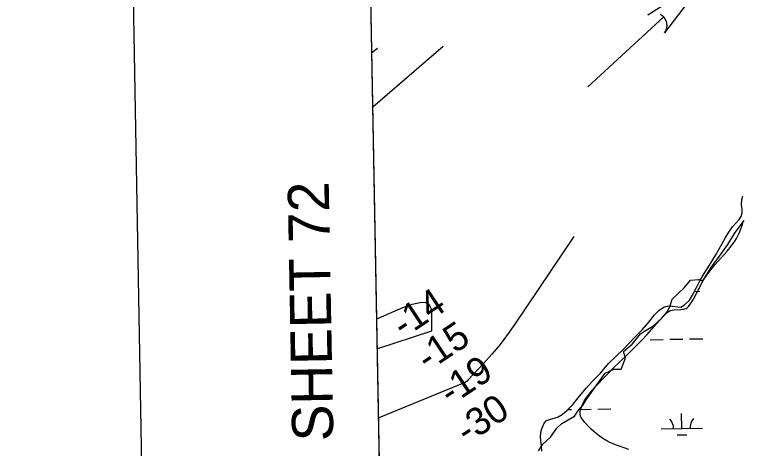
# Model space of a CAD drawing. Extents: x 3957609 to 3995875, y 234277 to 260273.
# Drawn here: x 3960953 to 3962722, y 241513 to 242568 of the extents above; entities that cross this region are included whole.
import ezdxf

# ---------------------------------------------------------------- set-up
doc = ezdxf.new("R2010")
doc.units = 0
for name, color, linetype in [('V-ANNO-SYMB', 7, 'Continuous'), ('V-ANNO-TEXT', 7, 'Continuous'), ('V-GRID-FRAM', 7, 'Continuous'), ('V-RIVR-EDGE', 7, 'Continuous'), ('V-RIVR-RANG', 7, 'Continuous'), ('V-SITE-VEGE', 7, 'Continuous'), ('V-STRM-FLOW', 7, 'Continuous'), ('V-TOPO-MINR', 7, 'Continuous'), ('V-WETL-SWMP', 7, 'Continuous')]:
    doc.layers.add(name, color=color, linetype=linetype)

msp = doc.modelspace()

# ---------------------------------------------------------------- linework, layer by layer
at = {"layer": 'V-ANNO-SYMB'}
msp.add_lwpolyline([(3961369.919, 235535.518), (3994447.652, 236136.973), (3994031.027, 259049.761), (3960953.294, 258448.306), (3961369.919, 235535.518)], dxfattribs=at)
at = {"layer": 'V-GRID-FRAM'}
for points in [[(3961534.646, 257877.621), (3993438.57, 258485.581), (3993792.928, 240306.336), (3961873.139, 239698.074), (3961534.646, 257877.621)], [(3961873.139, 239698.074), (3961534.646, 257877.621)]]:
    msp.add_lwpolyline(points, dxfattribs=at)
at = {"layer": 'V-RIVR-EDGE'}
msp.add_lwpolyline([(3962226.19, 241507.633), (3962236.605, 241523.729), (3962255.542, 241540.773), (3962270.692, 241562.551), (3962283.001, 241573.913), (3962313.301, 241591.904), (3962321.823, 241604.213), (3962335.079, 241619.363), (3962341.707, 241631.672), (3962388.103, 241696.059), (3962408.934, 241706.474), (3962426.925, 241706.474), (3962437.34, 241732.986), (3962432.606, 241749.083), (3962453.437, 241767.074), (3962474.268, 241791.692), (3962483.737, 241798.32), (3962503.621, 241810.629), (3962525.399, 241829.567), (3962539.602, 241846.61), (3962546.23, 241859.866), (3962550.964, 241875.963), (3962580.317, 241903.422), (3962595.467, 241922.359), (3962615.351, 241924.253), (3962625.767, 241920.466), (3962647.544, 241955.5), (3962665.535, 241981.065), (3962686.366, 242009.471), (3962702.463, 242035.983), (3962726.134, 242067.23)], dxfattribs=at)
at = {"layer": 'V-SITE-VEGE'}
for points in [[(3962370.457, 241546.306), (3962365.755, 241550.134), (3962360.42, 241554.803), (3962354.325, 241560.542), (3962351.063, 241563.79), (3962339.031, 241576.443), (3962336.374, 241579.496), (3962333.173, 241583.59), (3962331.574, 241585.941), (3962330.003, 241588.638), (3962328.594, 241591.733), (3962328.037, 241593.386), (3962327.605, 241595.151), (3962327.343, 241597.039), (3962327.308, 241599.055), (3962327.697, 241603.05), (3962328.469, 241607.095), (3962329.184, 241609.815), (3962330.368, 241613.462), (3962332.323, 241618.355), (3962335.252, 241624.364), (3962337.29, 241628.026), (3962339.823, 241632.197), (3962342.953, 241636.936), (3962346.782, 241642.294), (3962351.411, 241648.313), (3962356.916, 241655.01), (3962363.31, 241662.366), (3962372.462, 241672.424), (3962381.658, 241682.144), (3962396.02, 241696.72), (3962406.987, 241707.494), (3962441.037, 241740.27), (3962452.064, 241751.063), (3962464.569, 241763.665), (3962476.91, 241776.622), (3962489.063, 241789.816), (3962513.176, 241816.444), (3962529.403, 241834.009), (3962538.827, 241843.856), (3962541.009, 241845.742), (3962543.435, 241847.231), (3962545.174, 241848.03), (3962547.628, 241848.878), (3962551.097, 241849.683), (3962555.998, 241850.315), (3962571.931, 241851.096), (3962576.914, 241851.669), (3962579.445, 241852.171), (3962582.02, 241852.898), (3962584.594, 241853.94), (3962587.117, 241855.403), (3962588.317, 241856.316), (3962589.477, 241857.385), (3962590.58, 241858.628), (3962594.699, 241864.092), (3962598.52, 241869.755), (3962600.929, 241873.624), (3962603.995, 241878.877), (3962607.88, 241886.012), (3962619.345, 241908.548), (3962623.178, 241915.808), (3962627.799, 241923.906), (3962630.41, 241928.115), (3962633.334, 241932.494), (3962639.003, 241940.26), (3962644.998, 241947.849), (3962649.135, 241952.832), (3962654.793, 241959.408), (3962678.001, 241985.486), (3962684.493, 241993.055), (3962691.655, 242001.874), (3962695.327, 242006.672), (3962699.106, 242011.88), (3962702.952, 242017.547), (3962706.823, 242023.738), (3962710.646, 242030.529), (3962714.341, 242038.011), (3962717.077, 242044.572), (3962719.406, 242051.259), (3962720.776, 242055.773), (3962722.429, 242061.851)], [(3962445.723, 241510.536), (3962433.968, 241514.489), (3962420.619, 241519.324), (3962413.551, 241522.085), (3962406.066, 241525.191), (3962399.828, 241528.018), (3962393.823, 241531.045), (3962389.932, 241533.185), (3962384.867, 241536.193), (3962378.295, 241540.51), (3962374.615, 241543.142), (3962370.457, 241546.306)]]:
    msp.add_lwpolyline(points, dxfattribs=at)
at = {"layer": 'V-STRM-FLOW'}
msp.add_line((3962346.251, 242392.61), (3962530.315, 242562.375), dxfattribs=at)
msp.add_lwpolyline([(3962492.975, 242568.297), (3962492.524, 242568.04), (3962492.107, 242567.792), (3962491.807, 242567.608), (3962491.599, 242567.478), (3962634.402, 242658.376), (3962532.278, 242523.373), (3962533.983, 242525.893), (3962535.381, 242528.476), (3962535.872, 242529.553), (3962536.273, 242530.515), (3962536.71, 242531.703), (3962537.088, 242532.862), (3962537.376, 242533.879), (3962537.713, 242535.284), (3962538.001, 242536.811), (3962538.128, 242537.671), (3962538.255, 242538.782), (3962538.362, 242540.255), (3962538.394, 242541.402), (3962538.38, 242542.635), (3962538.344, 242543.45), (3962538.281, 242544.341), (3962538.166, 242545.425), (3962538.027, 242546.422), (3962537.854, 242547.41), (3962537.69, 242548.213), (3962537.407, 242549.401), (3962537.089, 242550.527), (3962536.804, 242551.419), (3962536.434, 242552.456), (3962536.083, 242553.345), (3962535.75, 242554.124), (3962535.473, 242554.719), (3962535.029, 242555.622), (3962534.544, 242556.532), (3962534.055, 242557.379), (3962533.529, 242558.224), (3962533.018, 242558.99), (3962532.434, 242559.809), (3962531.934, 242560.467), (3962531.188, 242561.386), (3962530.315, 242562.375), (3962530.027, 242562.684), (3962529.597, 242563.127), (3962529.075, 242563.643), (3962528.559, 242564.131), (3962528.045, 242564.591), (3962527.536, 242565.031), (3962526.921, 242565.535), (3962526.486, 242565.876), (3962525.837, 242566.362), (3962525.218, 242566.798), (3962524.785, 242567.093), (3962523.651, 242567.811), (3962523.03, 242568.177), (3962522.598, 242568.417)], dxfattribs=at)
at = {"layer": 'V-TOPO-MINR'}
for points in [[(3961835.051, 242485.777), (3961821.437, 242474.87)], [(3961994.802, 242490.319), (3961823.891, 242343.074)], [(3962312.267, 242028.666), (3962168.78, 241815.344), (3962151.092, 241790.354), (3962132.644, 241765.967), (3962113.056, 241742.487), (3962092.709, 241719.61), (3962054.797, 241678.978), (3962052.725, 241677.029), (3962050.514, 241675.28), (3962048.095, 241673.833), (3962045.537, 241672.586), (3961837.956, 241587.68)], [(3961833.471, 241828.528), (3961896.986, 241856.028), (3961907.983, 241860.303), (3961919.146, 241864.009), (3961930.557, 241866.862), (3961942.133, 241869.147), (3961951.265, 241867.945), (3961958.573, 241864.575), (3961963.142, 241857.951), (3961965.888, 241849.159), (3961966.611, 241800.306), (3961966.539, 241799.801), (3961966.38, 241799.34), (3961965.714, 241798.603), (3961963.759, 241797.654), (3961834.835, 241755.299)]]:
    msp.add_lwpolyline(points, dxfattribs=at)
at = {"layer": 'V-WETL-SWMP'}
for p, q in [((3962719.906, 242118.618), (3962722.332, 242126.735)), ((3962719.499, 242105.059), (3962719.906, 242118.618)), ((3962720.724, 242094.817), (3962719.499, 242105.059)), ((3962718.524, 242077.444), (3962721.276, 242086.39)), ((3962721.276, 242086.39), (3962720.724, 242094.817)), ((3962704.422, 242059.993), (3962713.449, 242069.971)), ((3962713.449, 242069.971), (3962718.524, 242077.444)), ((3962690.49, 242041.715), (3962697.366, 242052.011)), ((3962697.366, 242052.011), (3962704.422, 242059.993)), ((3962680.675, 242025.945), (3962690.49, 242041.715)), ((3962671.524, 242009.684), (3962680.675, 242025.945)), ((3962657.144, 241984.295), (3962671.524, 242009.684)), ((3962641.772, 241958.734), (3962657.144, 241984.295)), ((3962628.682, 241938.313), (3962641.772, 241958.734)), ((3962618.052, 241920.719), (3962628.682, 241938.313)), ((3962610.389, 241904.467), (3962618.052, 241920.719)), ((3962600.097, 241885.884), (3962610.389, 241904.467)), ((3962605.261, 241895.209), (3962618.349, 241895.447)), ((3962593.067, 241873.934), (3962600.097, 241885.884)), ((3962518.176, 241848.973), (3962531.839, 241857.825)), ((3962531.839, 241857.825), (3962543.73, 241859.722)), ((3962543.73, 241859.722), (3962571.856, 241856.436)), ((3962571.856, 241856.436), (3962580.911, 241862.116)), ((3962580.911, 241862.116), (3962593.067, 241873.934)), ((3962507.668, 241837.992), (3962518.176, 241848.973)), ((3962494.394, 241820.381), (3962507.668, 241837.992)), ((3962477.656, 241801.424), (3962494.394, 241820.381)), ((3962460.58, 241783.622), (3962477.656, 241801.424)), ((3962432.012, 241753.676), (3962460.58, 241783.622)), ((3962497.06, 241777.79), (3962529.054, 241778.372)), ((3962545.052, 241778.663), (3962577.046, 241779.245)), ((3962593.044, 241779.535), (3962625.038, 241780.117)), ((3962395.867, 241719.547), (3962432.012, 241753.676)), ((3962376.843, 241696.277), (3962395.867, 241719.547)), ((3962356.641, 241676.305), (3962376.843, 241696.277)), ((3962343.186, 241661.007), (3962356.641, 241676.305)), ((3962318.909, 241632.081), (3962329.566, 241645.542)), ((3962329.566, 241645.542), (3962343.186, 241661.007)), ((3962310.22, 241621.113), (3962318.909, 241632.081)), ((3962295.934, 241606.305), (3962310.22, 241621.113)), ((3962370.2, 241608.955), (3962402.195, 241609.537)), ((3962274.052, 241590.455), (3962283.442, 241595.477)), ((3962283.442, 241595.477), (3962295.934, 241606.305)), ((3962297.21, 241607.628), (3962306.211, 241607.791)), ((3962322.208, 241608.082), (3962354.203, 241608.664)), ((3962574.405, 241561.918), (3962573.75, 241597.912)), ((3962236.193, 241565.407), (3962240.101, 241574.526)), ((3962240.101, 241574.526), (3962245.678, 241581.175)), ((3962245.678, 241581.175), (3962255.077, 241584.874)), ((3962255.077, 241584.874), (3962263.988, 241587.248)), ((3962263.988, 241587.248), (3962274.052, 241590.455)), ((3962231.048, 241543.386), (3962232.945, 241556.624)), ((3962232.945, 241556.624), (3962236.193, 241565.407)), ((3962524.413, 241561.009), (3962624.397, 241562.827)), ((3962231.789, 241531.322), (3962231.048, 241543.386)), ((3962562.687, 241546.271), (3962586.683, 241546.707)), ((3962233.848, 241519.929), (3962231.789, 241531.322)), ((3962234.266, 241506.706), (3962233.848, 241519.929))]:
    msp.add_line(p, q, dxfattribs=at)
for centre, start, end in [((3962519.162, 241561.388), 0.269879, 41.813537), ((3962629.63, 241563.397), 140.269876, 181.813534)]:
    msp.add_arc(centre, 35.246, start, end, dxfattribs=at)

# ---------------------------------------------------------------- texts
at = {"layer": 'V-ANNO-TEXT'}
msp.add_text('JOINS SHEET 72', height=100, rotation=91.041702, dxfattribs=at).set_placement((3961735.838, 241100.638))
at = {"layer": 'V-RIVR-RANG'}
for s, p in [('-14', (3961898.03, 241779.812)), ('-15', (3961957.123, 241699.069)), ('-19', (3962012.67, 241616.022)), ('-30', (3962052.618, 241522.182))]:
    msp.add_text(s, height=67, rotation=33.645028, dxfattribs=at).set_placement(p)

doc.saveas('drawing.dxf')
